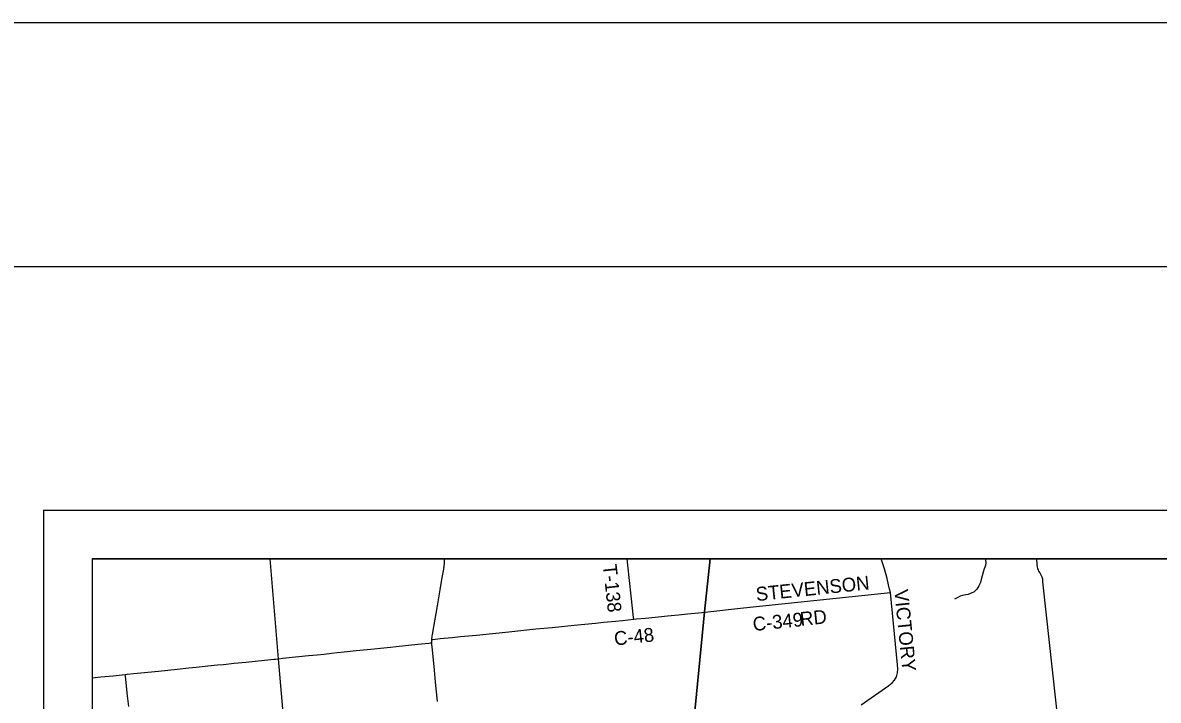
# Model space of a CAD drawing. Extents: x 0 to 34, y 0 to 22.
# Drawn here: x 1.957 to 4.289, y 20.61 to 22 of the extents above; entities that cross this region are included whole.
import ezdxf

# ---------------------------------------------------------------- set-up
doc = ezdxf.new("R2010")
doc.units = 0
for name, color, linetype in [('GM_X_Corporation', 7, 'Continuous'), ('GM_X_County_Road', 7, 'Continuous'), ('GM_X_County_Road_Text', 7, 'Continuous'), ('GM_X_Minor_River', 7, 'Continuous'), ('GM_X_Rail_Line', 7, 'Continuous'), ('GM_X_Township_Road', 7, 'Continuous'), ('GM_X_Township_Road_Text', 7, 'Continuous'), ('SH_Border', 7, 'Continuous'), ('SH_Cut_Line', 7, 'Continuous'), ('SH_Data', 7, 'Continuous')]:
    doc.layers.add(name, color=color, linetype=linetype)

msp = doc.modelspace()

# ---------------------------------------------------------------- linework, layer by layer
at = {"layer": 'GM_X_Corporation'}
for points in [[(2.8444, 15.5792), (2.8939, 16.1007), (2.9069, 16.2381), (2.9254, 16.4061), (2.988, 17.0603), (3.0331, 17.5172), (3.0637, 17.8164), (3.0931, 18.1263), (3.1112, 18.3014), (3.1559, 18.7686), (3.1859, 19.0395), (3.2287, 19.5029), (3.2417, 19.6403), (3.2592, 19.8236), (3.2953, 20.1573), (3.3575, 20.7908), (3.3687, 20.9), (2.1, 20.9), (2.1, 14.1)], [(8.9, 20.9), (3.3687, 20.9), (3.3575, 20.7908), (3.2953, 20.1573), (3.2592, 19.8236), (3.2417, 19.6403), (3.2287, 19.5029), (3.1859, 19.0395), (3.1559, 18.7686), (3.1112, 18.3014), (3.0931, 18.1263), (3.0637, 17.8164), (3.0331, 17.5172), (2.988, 17.0603), (2.9254, 16.4061), (2.9069, 16.2381), (2.8939, 16.1007), (2.8444, 15.5792)]]:
    msp.add_lwpolyline(points, dxfattribs=at)
msp.add_lwpolyline([(3.3687, 20.9), (2.1, 20.9), (2.1, 18.2085), (2.1311, 18.2055), (2.4093, 18.1831), (2.8083, 18.1509), (3.0252, 18.1335), (3.0931, 18.1263), (3.1112, 18.3014), (3.1559, 18.7686), (3.1859, 19.0395), (3.2287, 19.5029), (3.2417, 19.6403), (3.2592, 19.8236), (3.2953, 20.1573), (3.3575, 20.7908)], close=True, dxfattribs=at)
at = {"layer": 'GM_X_County_Road'}
for points in [[(2.7974, 20.7345), (2.7975, 20.7366), (2.7977, 20.739), (2.798, 20.742), (2.7984, 20.7446), (2.8086, 20.8034), (2.8144, 20.8365), (2.8188, 20.8616), (2.8217, 20.8787), (2.8221, 20.8815), (2.8223, 20.8836), (2.8227, 20.8864), (2.823, 20.8898), (2.8232, 20.8929), (2.8233, 20.8963), (2.8233, 20.8991), (2.8233, 20.9)], [(3.6791, 20.6001), (3.7358, 20.6402), (3.7423, 20.6456), (3.7472, 20.651), (3.7513, 20.6578), (3.7539, 20.6661), (3.7543, 20.6739), (3.7539, 20.6824), (3.7389, 20.8307), (3.7373, 20.8374), (3.7353, 20.8466), (3.7321, 20.8596), (3.7272, 20.8792), (3.72, 20.8998), (3.7199, 20.9)], [(4.1832, 19.5969), (4.1649, 19.7889), (4.1121, 20.3045), (4.0523, 20.8528), (4.0517, 20.8579), (4.0504, 20.8623), (4.0487, 20.8664), (4.0471, 20.869), (4.0456, 20.8717), (4.0441, 20.8746), (4.043, 20.877), (4.0421, 20.8795), (4.0414, 20.8832), (4.0405, 20.8879), (4.0401, 20.8922), (4.0393, 20.9)], [(3.3576, 20.7906), (3.4372, 20.7994), (3.7389, 20.8307)], [(2.7974, 20.7345), (2.7992, 20.7346), (2.8141, 20.7362), (2.8389, 20.7387), (2.8562, 20.7403), (2.8889, 20.7435), (2.9217, 20.7468), (2.9551, 20.7502), (2.9674, 20.7515), (3.0107, 20.7559), (3.0447, 20.7591), (3.0636, 20.7609), (3.0896, 20.7635), (3.1334, 20.768), (3.1498, 20.7697), (3.1743, 20.7719), (3.1888, 20.7733), (3.2118, 20.7758), (3.2175, 20.7765), (3.2358, 20.7782), (3.2691, 20.7814), (3.2815, 20.7827), (3.3038, 20.785), (3.322, 20.7868), (3.3446, 20.7891), (3.3525, 20.7899), (3.3576, 20.7906)], [(2.7973, 20.7277), (2.7973, 20.7281), (2.7973, 20.7302), (2.7973, 20.7321), (2.7973, 20.7338), (2.7974, 20.7345)], [(2.1, 20.6556), (2.1172, 20.6574), (2.1431, 20.66), (2.1678, 20.6626), (2.1716, 20.663), (2.1845, 20.6644), (2.1997, 20.666), (2.2359, 20.6695), (2.2742, 20.6735), (2.2983, 20.6761), (2.3134, 20.6776), (2.3317, 20.6795), (2.3374, 20.6801), (2.357, 20.682), (2.3692, 20.6833), (2.3801, 20.6845), (2.3912, 20.6856), (2.4155, 20.6879), (2.4346, 20.6898), (2.4668, 20.6931), (2.4729, 20.6938), (2.4763, 20.6942), (2.4828, 20.6949), (2.4904, 20.6957), (2.4975, 20.6965), (2.5437, 20.7012), (2.562, 20.703), (2.5762, 20.7045), (2.591, 20.7061), (2.6027, 20.7073), (2.6175, 20.7088), (2.6416, 20.7114), (2.6717, 20.7144), (2.6985, 20.7171), (2.7122, 20.7185), (2.7242, 20.7197), (2.7687, 20.7245), (2.7909, 20.7269), (2.7936, 20.7272), (2.7973, 20.7277)], [(2.8092, 20.607), (2.8051, 20.6465), (2.8025, 20.6712), (2.7979, 20.7201), (2.7976, 20.7232), (2.7974, 20.726), (2.7973, 20.7277)], [(2.1749, 20.5969), (2.1726, 20.6185), (2.1697, 20.6454), (2.1681, 20.6599), (2.1678, 20.6626)]]:
    msp.add_lwpolyline(points, dxfattribs=at)
at = {"layer": 'GM_X_Minor_River'}
msp.add_lwpolyline([(3.934, 20.9), (3.9343, 20.8973), (3.935, 20.8923), (3.9345, 20.8859), (3.9316, 20.8793), (3.9294, 20.8727), (3.9255, 20.8576), (3.9237, 20.8515), (3.9208, 20.8442), (3.9167, 20.8374), (3.9113, 20.8321), (3.9037, 20.8288), (3.8988, 20.8268), (3.8937, 20.8259), (3.8872, 20.8247), (3.8821, 20.8229), (3.8772, 20.8208), (3.8707, 20.8173)], dxfattribs=at)
at = {"layer": 'GM_X_Rail_Line'}
msp.add_lwpolyline([(2.4962, 20.5367), (2.4826, 20.6948), (2.4651, 20.9)], dxfattribs=at)
at = {"layer": 'GM_X_Township_Road'}
msp.add_lwpolyline([(3.2118, 20.7758), (3.2114, 20.7792), (3.2064, 20.824), (3.1995, 20.8868), (3.1981, 20.9)], dxfattribs=at)
at = {"layer": 'SH_Border'}
msp.add_lwpolyline([(1.5, 21.5), (33.5, 21.5), (33.5, 0.5), (1.5, 0.5)], close=True, dxfattribs=at)
at = {"layer": 'SH_Cut_Line'}
msp.add_lwpolyline([(0, 0), (34, 0), (34, 22), (0, 22)], close=True, dxfattribs=at)
at = {"layer": 'SH_Data'}
for p, q in [((2, 21), (9, 21)), ((2, 21), (2, 14)), ((2.1, 20.9), (2.1, 14.1)), ((2.1, 20.9), (8.9, 20.9))]:
    msp.add_line(p, q, dxfattribs=at)

# ---------------------------------------------------------------- texts
at = {"layer": 'GM_X_County_Road_Text'}
for s, rotation, p in [('STEVENSON', 5.9097, (3.4641, 20.813)), ('VICTORY', 275.7273, (3.7469, 20.8356)), ('C-349', 5.7917, (3.4578, 20.7515)), ('RD', 5.9576, (3.555, 20.762)), ('C-48', 6.1522, (3.1731, 20.7218))]:
    msp.add_text(s, height=0.02841, rotation=rotation, dxfattribs=at).set_placement(p)
at = {"layer": 'GM_X_Township_Road_Text'}
msp.add_text('T-138', height=0.02841, rotation=276.1851, dxfattribs=at).set_placement((3.1484, 20.8873))

doc.saveas('drawing.dxf')
